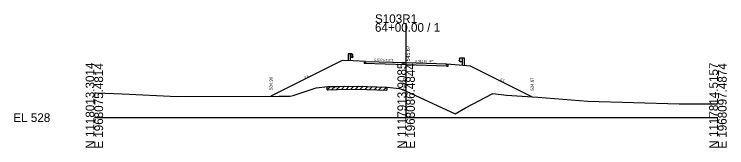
# Model space of a CAD drawing. Extents: x -26 to 203, y -10 to 12018.
# Drawn here: x -25.7 to 202.8, y 4490.3 to 4533.2 of the extents above; entities that cross this region are included whole.
import ezdxf

# ---------------------------------------------------------------- set-up
doc = ezdxf.new("R2010")
doc.units = 0
for name, color, linetype in [('Level 10', 7, 'Continuous'), ('Level 11', 7, 'Continuous'), ('Level 12', 7, 'Continuous'), ('Level 24', 7, 'Continuous'), ('Level 32', 7, 'Continuous'), ('Level 33', 7, 'Continuous'), ('Level 59', 7, 'Continuous'), ('Level 6', 7, 'Continuous'), ('Level 60', 7, 'Continuous'), ('Level 61', 7, 'Continuous'), ('Level 63', 7, 'Continuous'), ('Level 7', 7, 'Continuous')]:
    doc.layers.add(name, color=color, linetype=linetype)

msp = doc.modelspace()

# ---------------------------------------------------------------- linework, layer by layer
at = {"layer": 'Level 11'}
for p, q in [((113, 4516.95), (113, 4517.26)), ((113.5, 4516.93), (113, 4516.95)), ((113, 4516.59), (113.5, 4516.57)), ((113.5, 4516.57), (113.5, 4516.93))]:
    msp.add_line(p, q, dxfattribs=at)
at = {"layer": 'Level 12'}
for p, q in [((86.5, 4517.79), (87, 4517.77)), ((86.5, 4517.79), (86.5, 4517.43)), ((100, 4517), (86.5, 4517.43)), ((87, 4518.08), (87, 4517.77)), ((113, 4516.59), (100, 4517))]:
    msp.add_line(p, q, dxfattribs=at)
at = {"layer": 'Level 24'}
for p, q in [((81.4, 4520.46), (81.4, 4518.26)), ((82.06, 4520.46), (81.4, 4520.46)), ((82.06, 4520.46), (82.06, 4518.24)), ((82.73, 4520.46), (82.06, 4520.46)), ((82.73, 4519.29), (82.73, 4520.46)), ((82.73, 4520.39), (83, 4520.19)), ((82.73, 4519.29), (82.06, 4519.29)), ((83, 4520.14), (82.73, 4519.94)), ((83, 4519.61), (82.73, 4519.81)), ((82.73, 4519.36), (83, 4519.56)), ((83, 4520.19), (83, 4520.14)), ((83, 4519.56), (83, 4519.61)), ((117.27, 4519.1), (117, 4518.9)), ((117, 4518.9), (117, 4518.85)), ((117, 4518.85), (117.27, 4518.65)), ((117, 4518.33), (117.27, 4518.53)), ((117, 4518.28), (117, 4518.33)), ((117.27, 4518.08), (117, 4518.28)), ((117.27, 4518.01), (117.27, 4519.18)), ((117.27, 4519.18), (117.94, 4519.18)), ((117.94, 4519.18), (117.94, 4516.85)), ((117.94, 4519.18), (118.6, 4519.18)), ((118.6, 4519.18), (118.6, 4516.79)), ((117.27, 4518.01), (117.94, 4518.01))]:
    msp.add_line(p, q, dxfattribs=at)
at = {"layer": 'Level 59'}
for p, q in [((87, 4518.08), (100, 4517.67)), ((100, 4517.67), (113, 4517.26))]:
    msp.add_line(p, q, dxfattribs=at)
at = {"layer": 'Level 6'}
for p, q in [((83, 4518.21), (79.5, 4518.32)), ((87, 4518.08), (83, 4518.21)), ((113, 4517.26), (117, 4516.93)), ((117, 4516.93), (120.5, 4516.64))]:
    msp.add_line(p, q, dxfattribs=at)
at = {"layer": 'Level 60'}
for p, q in [((63.73, 4507.13), (71.14, 4509.61)), ((71.14, 4509.61), (74.85, 4509.98)), ((74.85, 4509.98), (77.88, 4510.03)), ((77.88, 4510.03), (84.32, 4510.13)), ((84.32, 4510.13), (93.91, 4509.83)), ((93.91, 4509.83), (97.85, 4509.34)), ((97.85, 4509.34), (98.18, 4509.29)), ((98.18, 4509.29), (100, 4508.47)), ((0, 4507.93), (0.53, 4507.92)), ((0.53, 4507.92), (8.89, 4507.68)), ((8.89, 4507.68), (26.58, 4506.78)), ((26.58, 4506.78), (59.15, 4506.91)), ((59.15, 4506.91), (62.86, 4506.89)), ((62.86, 4506.89), (63.73, 4507.13)), ((100, 4508.47), (115.71, 4501.27)), ((119.06, 4503.19), (127.76, 4507.76)), ((127.76, 4507.76), (132.2, 4507.25)), ((132.2, 4507.25), (142.24, 4506.54)), ((142.24, 4506.54), (158.24, 4505.31)), ((158.24, 4505.31), (187.57, 4504.43)), ((187.57, 4504.43), (199.92, 4504.48)), ((115.71, 4501.27), (119.06, 4503.19))]:
    msp.add_line(p, q, dxfattribs=at)
at = {"layer": 'Level 61'}
for p, q in [((74.72, 4508.96), (75.75, 4509.99)), ((74.72, 4508.96), (74.72, 4509.96)), ((74.72, 4508.96), (74.85, 4508.98)), ((74.85, 4508.98), (77.88, 4509.03)), ((76.22, 4509), (77.23, 4510.02)), ((77.72, 4509.02), (78.73, 4510.04)), ((77.88, 4509.03), (84.32, 4509.13)), ((79.22, 4509.05), (80.23, 4510.07)), ((80.72, 4509.07), (81.73, 4510.09)), ((82.22, 4509.1), (83.23, 4510.12)), ((83.72, 4509.12), (84.72, 4510.12)), ((84.32, 4509.13), (93.79, 4508.84)), ((85.22, 4509.11), (86.19, 4510.08)), ((86.72, 4509.06), (87.69, 4510.03)), ((88.22, 4509.01), (89.19, 4509.98)), ((89.72, 4508.97), (90.69, 4509.93)), ((91.22, 4508.92), (92.19, 4509.89)), ((92.72, 4508.87), (93.69, 4509.84)), ((93.79, 4509.84), (93.79, 4508.84))]:
    msp.add_line(p, q, dxfattribs=at)
at = {"layer": 'Level 63'}
for p, q in [((100, 4500), (100, 4530.4)), ((0, 4500), (100, 4500)), ((100, 4500), (200, 4500))]:
    msp.add_line(p, q, dxfattribs=at)
at = {"layer": 'Level 7'}
for p, q in [((79.5, 4518.32), (56.65, 4506.9)), ((120.5, 4516.64), (140.44, 4506.67))]:
    msp.add_line(p, q, dxfattribs=at)

# ---------------------------------------------------------------- texts
at = {"layer": 'Level 10'}
msp.add_text(' 536.47', height=0.9, rotation=90, dxfattribs=at).set_placement((99.95, 4508.63))
at = {"layer": 'Level 32'}
for s, rotation, p in [('0.032 FT./FT.', 358.1901, (89.84, 4518.24)), ('0.032 FT./FT.', 358.1901, (102.84, 4517.83)), ('2:1', 26.5651, (67.46, 4512.58)), ('2:1', 333.4349, (130.08, 4512.13))]:
    msp.add_text(s, height=0.75, rotation=rotation, dxfattribs=at).set_placement(p)
at = {"layer": 'Level 33'}
for s, p in [('534.90', (57.15, 4508.9)), ('534.67', (140.94, 4508.67))]:
    msp.add_text(s, height=1, rotation=90, dxfattribs=at).set_placement(p)
at = {"layer": 'Level 59'}
msp.add_text(' 545.67', height=1.2, rotation=90, dxfattribs=at).set_placement((101.2, 4517.67))
at = {"layer": 'Level 63'}
for s, p in [('S103R1', (90, 4530.4)), ('64+00.00 / 1', (90, 4527.6)), ('EL 528', (-26, 4498.6))]:
    msp.add_text(s, height=2.8, dxfattribs=at).set_placement(p)
for s, p in [('N 1118013.3014', (0, 4490)), ('E 1968075.4814', (2.8, 4490)), ('N 1117913.9085', (100, 4490)), ('E 1968086.4844', (102.8, 4490)), ('N 1117814.5157', (200, 4490)), ('E 1968097.4874', (202.8, 4490))]:
    msp.add_text(s, height=2.8, rotation=90, dxfattribs=at).set_placement(p)

doc.saveas('drawing.dxf')
